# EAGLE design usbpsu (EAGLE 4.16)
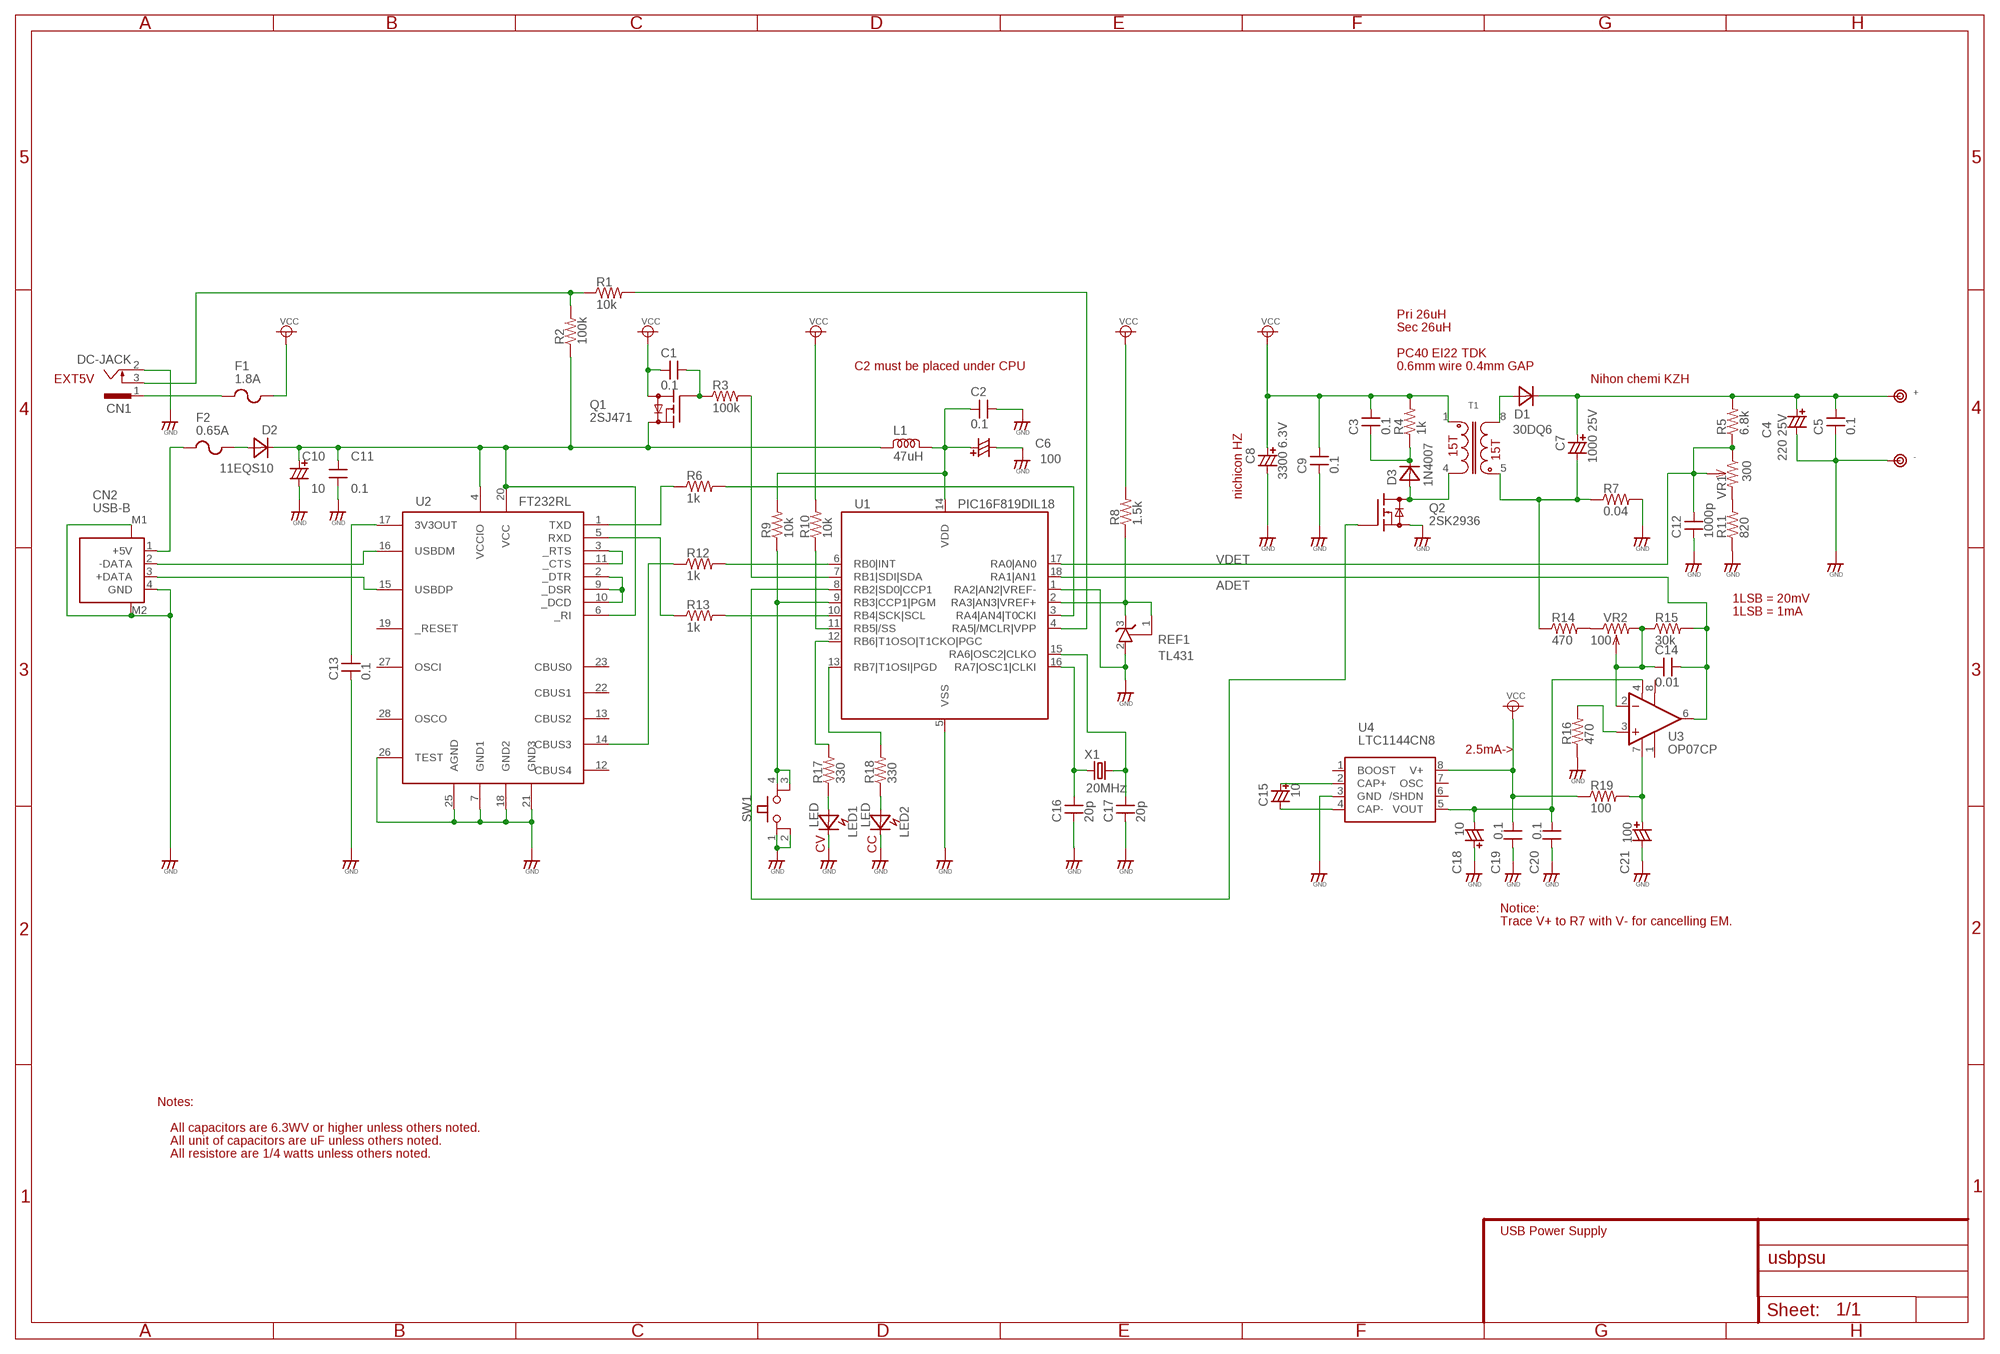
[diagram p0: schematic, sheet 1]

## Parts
+  TERM  [TERM_ARMY]
-  TERM  [TERM_ARMY]
C1  0.1  CAPDIP_2  [CAP_DIP_2]
C2  0.1  CAPSM2012  [C2012]
C3  0.1  CAPDIP_2  [CAP_DIP_2]
C4  220 25V  CCAP8  [CCAP_8]
C5  0.1  CAPDIP_2  [CAP_DIP_2]
C6  100  CCAP5.2  [CCAP_5.2]
C7  1000 25V  CCAP10.5  [CCAP_10.5]
C8  3300 6.3V  CCAP10.5  [CCAP_10.5]
C9  0.1  CAPDIP_2  [CAP_DIP_2]
C10  10  CCAP5.2  [CCAP_5.2]
C11  0.1  CAPDIP_2  [CAP_DIP_2]
C12  1000p  CAPDIP_2  [CAP_DIP_2]
C13  0.1  CAPDIP_2  [CAP_DIP_2]
C14  0.01  CAPDIP_2  [CAP_DIP_2]
C15  10  CCAP5.2  [CCAP_5.2]
C16  20p  CAPDIP_1  [CAP_DIP_1]
C17  20p  CAPDIP_1  [CAP_DIP_1]
C18  10  CCAP5.2  [CCAP_5.2]
C19  0.1  CAPDIP_2  [CAP_DIP_2]
C20  0.1  CAPDIP_2  [CAP_DIP_2]
C21  100  CCAP5.2  [CCAP_5.2]
CN1  DC-JACK  DC-JACK2DC0005D100  [2DC0005D100]
CN2  USB-B  [85-32004-00X]
D1  30DQ6  DIODEGENERIC_5  [DIODE_5]
D2  11EQS10  DIODEGENERIC_2  [DIODE_2]
D3  1N4007  DIODEGENERIC_3  [DIODE_3]
F1  1.8A  POLYSW10X3MM  [AX_10X03_2P_200]
F2  0.65A  POLYSW8X2MM  [AX_08X02_2P_200]
L1  47uH  MICRO_INDUCTOR  [LAL02]
LED1  LED  [LED_3MM_VIRT_2]
LED2  LED  [LED_3MM_VIRT_2]
Q1  2SJ471  [TO220-VIRT]
Q2  2SK2936  [TO220-VIRT]
R1  10k  R0.125W_2P  [R_0.125W_2]
R2  100k  R0.125W_2P  [R_0.125W_2]
R3  100k  R0.125W_2P  [R_0.125W_2]
R4  1k  R0.125W_2P  [R_0.125W_2]
R5  6.8k  R0.125W_2P  [R_0.125W_2]
R6  1k  R0.125W_2P  [R_0.125W_2]
R7  0.04  RSMD6332  [R6332]
R8  1.5k  R0.125W_2P  [R_0.125W_2]
R9  10k  R0.125W_2P  [R_0.125W_2]
R10  10k  R0.125W_2P  [R_0.125W_2]
R11  820  R0.125W_2P  [R_0.125W_2]
R12  1k  R0.125W_2P  [R_0.125W_2]
R13  1k  R0.125W_2P  [R_0.125W_2]
R14  470  R0.125W_2P  [R_0.125W_2]
R15  30k  R0.125W_2P  [R_0.125W_2]
R16  470  R0.125W_2P  [R_0.125W_2]
R17  330  R0.125W_2P  [R_0.125W_2]
R18  330  R0.125W_2P  [R_0.125W_2]
R19  100  R0.125W_2P  [R_0.125W_2]
REF1  TL431  TL431CLP  [TO92]
SW1  PUSHSW-6MM  [PUSHSW-6MM]
T1  TRANS  [TDK_BE22]
U1  PIC16F819DIL18  [DIL18]
U2  FT232RL  [SSOP28DB]
U3  OP07CP  [DIL08]
U4  LTC1144CN8  [DIL08]
VR1  300  VR  [VR-7MM]
VR2  100  VR  [VR-7MM]
X1  20MHz  CRYSTALHC49S  [HC49/S]

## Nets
/BUSPWR: R3.2 U1.7(RB1|SDI|SDA)
/PWREN: R12.1 U2.14(CBUS3)
ADET: C14.2 R15.2 U1.18(RA1|AN1) U3.6(OUT)
DVCC: C1.1 C3.2 C8.+ C9.2 C19.2 F1.2 Q1.2(D) R4.2 R8.2 R10.2 R19.1 T1.1 U4.8(V+) ; supply symbol labelled VCC
EXTDET: R1.2 U1.4(RA5|/MCLR|VPP)
GND: -.1(TERM) C2.2 C4.- C5.1 C6.- C8.- C9.1 C10.- C11.1 C12.1 C13.1 C16.1 C17.1 C18.+ C19.1 C20.1 C21.- CN1.2 CN2.4(GND) CN2.M1(FG1) CN2.M2(FG2) LED1.K LED2.K Q2.3(S) R7.2 R11.1 R16.1 REF1.2(A) SW1.1 SW1.2 U1.1(RA2|AN2|VREF-) U1.5(VSS) U2.7(GND1) U2.18(GND2) U2.21(GND3) U2.25(AGND) U2.26(TEST) U4.3(GND)
N$1: CN1.3 R1.1 R2.2
N$2: R9.1 SW1.3 SW1.4 U1.9(RB3|CCP1|PGM)
N$3: C13.2 U2.17(3V3OUT)
N$4: C18.- C20.2 U3.4(V-) U4.5(VOUT)
N$5: C2.1 C6.+ L1.2 R9.2 U1.14(VDD)
N$6: LED1.A R17.1
N$7: C16.2 U1.16(RA7|OSC1|CLKI) X1.1
N$8: C17.2 U1.15(RA6|OSC2|CLKO) X1.2
N$9: LED2.A R18.1
N$10: C21.+ R19.2 U3.7(V+)
N$11: U2.3(_RTS) U2.11(_CTS)
N$12: R17.2 U1.12(RB6|T1OSO|T1CKO|PGC)
N$13: R18.2 U1.13(RB7|T1OSI|PGD)
N$14: C15.+ U4.2(CAP+)
N$15: C15.- U4.4(CAP-)
N$16: C10.+ C11.2 D2.K L1.1 Q1.3(S) R2.1 U2.4(VCCIO) U2.6(_RI) U2.20(VCC)
N$17: C3.1 D3.K R4.1
N$18: R14.2 VR2.1
N$19: +.1(TERM) C4.+ C5.2 C7.+ D1.K R5.2
N$20: C14.1 R15.1 U3.2(-IN) VR2.2 VR2.3
N$21: D3.A Q2.2(D) T1.4(P2)
N$22: C1.2 Q1.1(G) R3.1
N$23: R6.1 U2.1(TXD)
N$24: R12.2 U1.6(RB0|INT)
N$25: D1.A T1.8(S1)
N$26: D2.A F2.2
N$27: R13.2 U1.10(RB4|SCK|SCL)
N$28: CN2.1(+5V) F2.1
N$30: C7.- R7.1 R14.1 T1.5(S2)
N$31: R8.1 REF1.1(R) REF1.3(C) U1.2(RA3|AN3|VREF+)
N$33: R11.2 VR1.3
N$34: R16.2 U3.3(+IN)
N$35: CN1.1 F1.1
N$36: U2.2(_DTR) U2.9(_DSR) U2.10(_DCD)
N$37: R10.1 U1.11(RB5|/SS)
PWM: Q2.1(G) U1.8(RB2|SD0|CCP1)
RXD: R13.1 U2.5(RXD)
TXD: R6.2 U1.3(RA4|AN4|T0CKI)
USB+: CN2.3(+DATA) U2.15(USBDP)
USB-: CN2.2(-DATA) U2.16(USBDM)
VDET: C12.2 R5.1 U1.17(RA0|AN0) VR1.1 VR1.2
Unconnected: U2.12(CBUS4) U2.13(CBUS2) U2.19(_RESET) U2.22(CBUS1) U2.23(CBUS0) U2.27(OSCI) U2.28(OSCO) U3.1(TRIM1) U3.8(TRIM2) U4.1(BOOST) U4.6(/SHDN) U4.7(OSC)

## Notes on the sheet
- Pri 26uH
- Sec 26uH
- PC40 EI22 TDK
- C2 must be placed under CPU | 0.6mm wire 0.4mm GAP
- EXT5V | Nihon chemi KZH
- 15T
- 15T
- nichicon HZ
- 1LSB = 20mV
- 1LSB = 1mA
- 2.5mA->
- CV | CC
- Notice:
- Trace V+ to R7 with V- for cancelling EM.
- Notes:
- All capacitors are 6.3WV or higher unless others noted.
- All unit of capacitors are uF unless others noted.
- All resistore are 1/4 watts unless others noted.
- USB Power Supply

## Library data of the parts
+ - = usbpsu:TERM
C1-C3 C5 C9 C11-C14 C16 C17 C19 C20 = usbpsu:CAP: Non polar capacitor
C4 C6-C8 C10 C15 C18 C21 = usbpsu:CCAP: Polar capacitor
CN1 = usbpsu:DC-JACK
CN2 = usbpsu:USB-B: USB-B Connector
D1-D3 = usbpsu:DIODE
F1 F2 = usbpsu:POLYSW
L1 = usbpsu:MICRO_INDUCTOR
LED1 LED2 = usbpsu:LED
Q1 = usbpsu:2SJ471
Q2 = usbpsu:2SK2936
R1-R19 = usbpsu:R
REF1 = usbpsu:TL431CLP: VOLTAGE REGULATOR
SW1 = usbpsu:PUSHSW-6MM
T1 = usbpsu:TRANS
U1 = usbpsu:PIC16F819: PIC MICRO (16 I/O 10bit-5ch ADC 20MHz)
U2 = ftdichip:FT232RL: USB UART 4th Generation USB UART (USB <-> Serial) Controller
U3 = usbpsu:OP07C
U4 = usbpsu:LTC1144
VR1 VR2 = usbpsu:VR
X1 = usbpsu:CRYSTAL: CRYSTAL

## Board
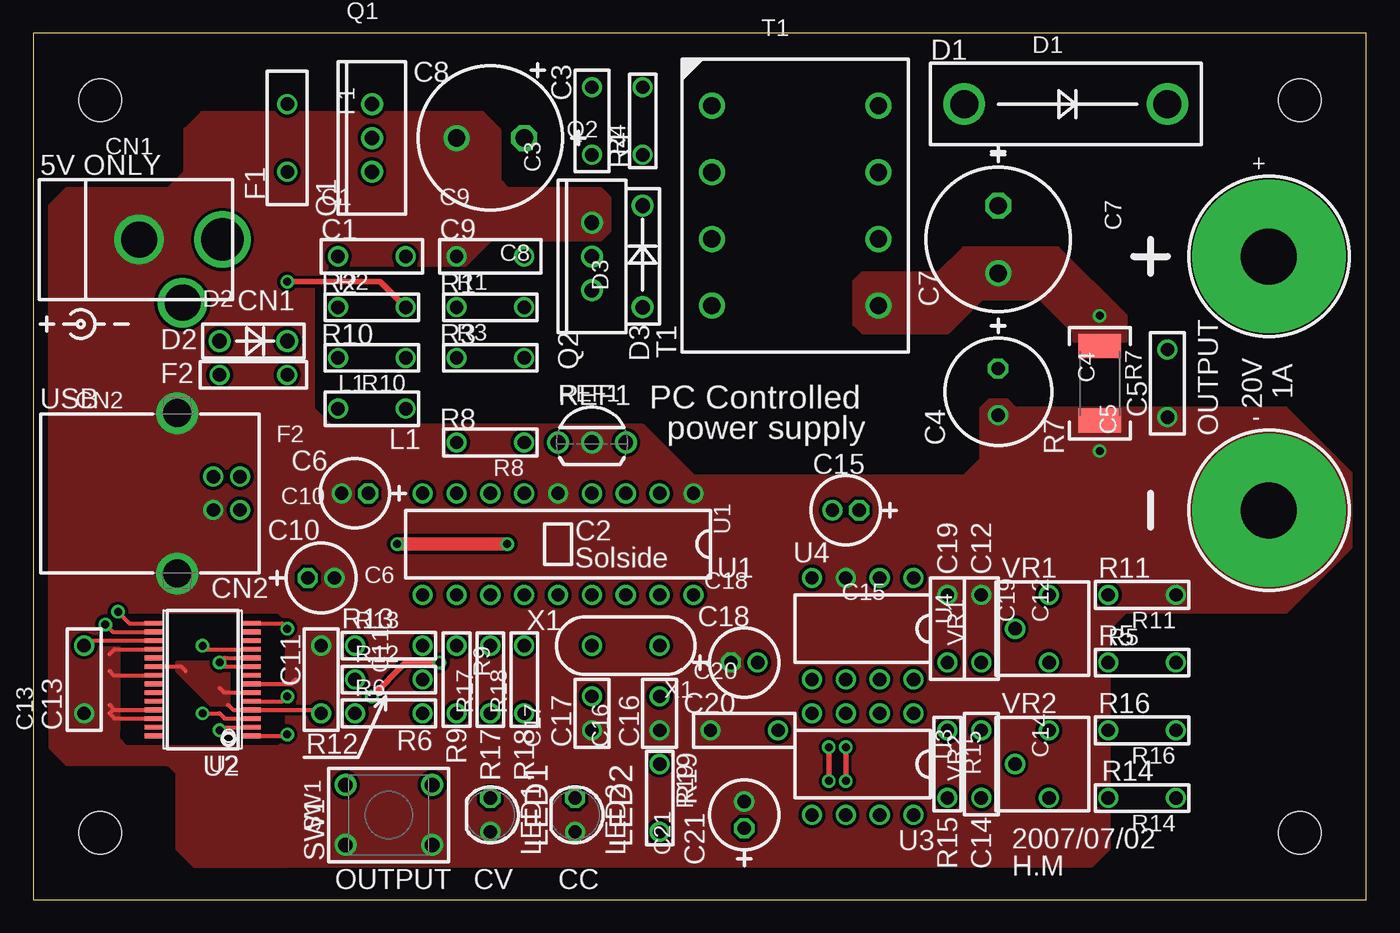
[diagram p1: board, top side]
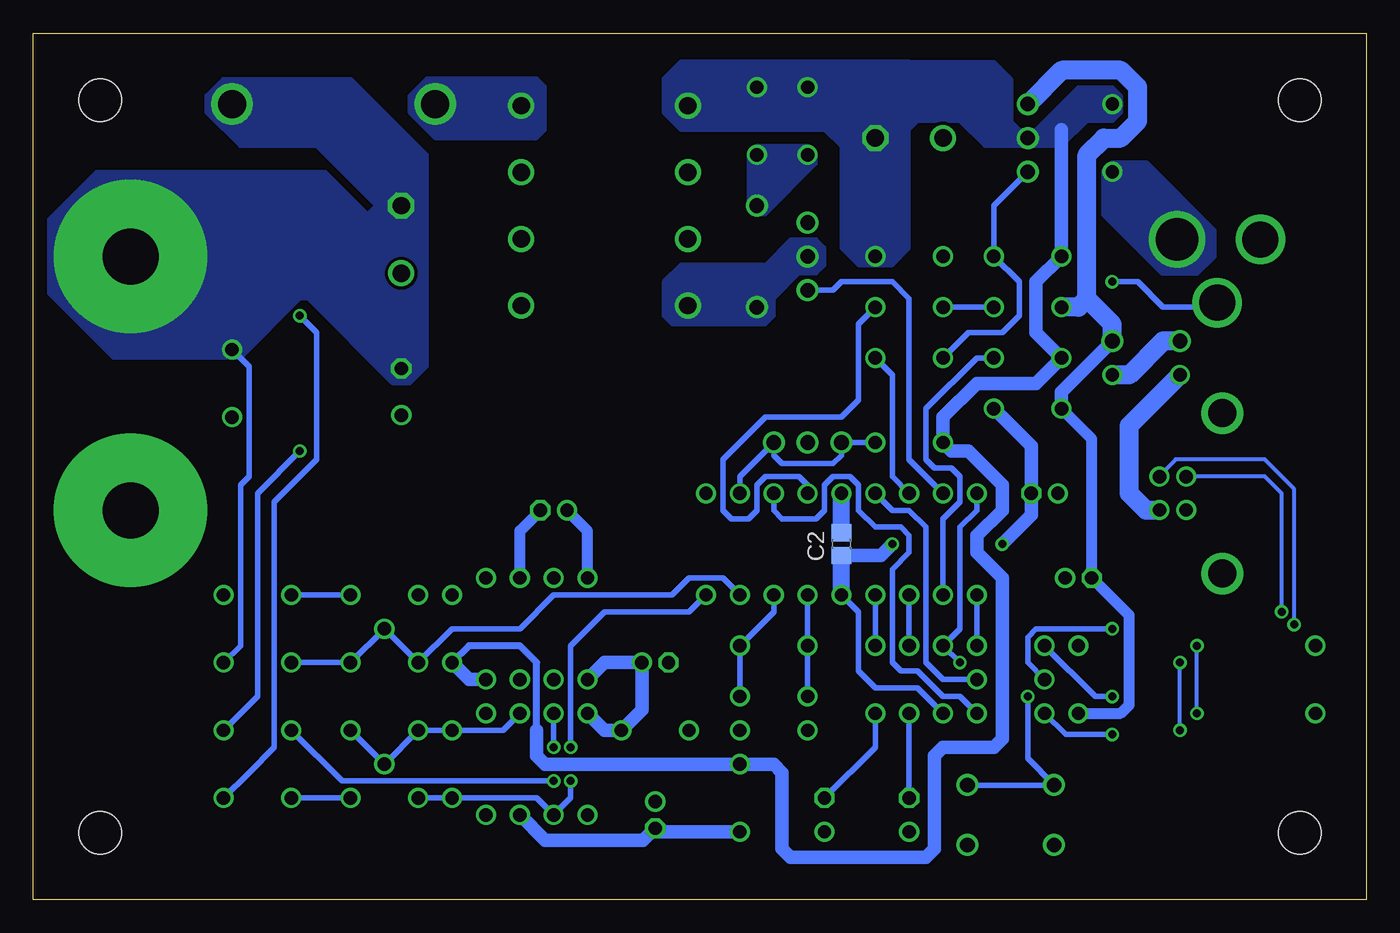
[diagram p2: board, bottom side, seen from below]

Size 100 x 65 mm. Coordinates in mm from the lower left corner, seen from the top.
Outline: 0,0 100,0 100,65 0,65 0,0
Copper layers (1*16): Top 0.035mm / dielectric 1.5mm / Bottom 0.035mm
Design rules "Olimex10mils": minimum track width 10mil, minimum drill 0.6mm, track to track 10mil, track to pad 10mil, pad to pad 10mil, via to via 10mil, smd to smd 10mil, copper to edge 40mil, drill to drill 10mil, minimum pad ring 10mil, minimum via ring 8mil, stop-mask expansion 0mil, vias tented up to drill 0mil, thermal gap 10mil
Holes 3.2 mm at 95,60 95,5 5,5 5,60
tRestrict: area 90,55 to 100,65; area 90,0 to 100,10; area 0,0 to 10,10; area 0,55 to 10,65
bRestrict: area 0,55 to 10,65; area 0,0 to 10,10; area 90,55 to 100,65; area 90,0 to 100,10

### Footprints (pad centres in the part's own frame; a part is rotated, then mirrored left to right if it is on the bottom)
TERM_ARMY = drill 4.2 pad 11.5 round: 1 0,0
CAP_DIP_2 = drill 1 round: 1 -2.54,0; 2 2.54,0
C2012 = smd 1.3 x 1.5: 1 -0.85,0; 2 0.85,0
CCAP_8 = drill 1 octagon: + -1.75,0 | drill 1 round: - 1.75,0
CCAP_5.2 = drill 1 octagon: + -1,0 | drill 1 round: - 1,0
CCAP_10.5 = drill 1.3 octagon: + -2.54,0 | drill 1.3 round: - 2.54,0
CAP_DIP_1 = drill 1 round: 1 -1.27,0; 2 1.27,0
2DC0005D100 = drill 3.2 round: 1 6.25,0 | drill 2.7 round: 2 0,0; 3 3.25,-4.75
85-32004-00X = drill 1 round: 1 4.71,-1.25; 2 4.71,1.25; 3 2.71,1.25; 4 2.71,-1.25 | drill 2.1 round: M1 0,6.02; M2 0,-6.02
DIODE_5 = drill 2.1 round: A -7.62,0; K 7.62,0
DIODE_2 = drill 1.1 round: A -2.54,0; K 2.54,0
DIODE_3 = drill 1.1 round: A -3.81,0; K 3.81,0
AX_10X03_2P_200 = drill 1 round: 1 2.54,0; 2 -2.54,0
AX_08X02_2P_200 = drill 1 round: 1 2.54,0; 2 -2.54,0
LAL02 = drill 1 round: 1 -2.54,0; 2 2.54,0
LED_3MM_VIRT_2 = drill 1 octagon: A -1.27,0 | drill 1 round: K 1.27,0
TO220-VIRT = drill 1.1 round: 1 0,-2.54; 2 0,0; 3 0,2.54
R_0.125W_2 = drill 1 round: 1 -2.54,0; 2 2.54,0
R6332 = smd 1.8 x 3.2: 1 -2.8,0; 2 2.8,0
TO92 = drill 1.1 round: 1 -2.54,0; 2 0,0; 3 2.54,0
PUSHSW-6MM = drill 1.1 round: 1 -2.25,3.25; 2 -2.25,-3.25; 3 2.25,-3.25; 4 2.25,3.25
TDK_BE22 = drill 1.3 round: 1 -6.25,7.5; 2 -6.25,2.5; 3 -6.25,-2.5; 4 -6.25,-7.5; 5 6.25,-7.5; 6 6.25,-2.5; 7 6.25,2.5; 8 6.25,7.5
DIL18 = drill 1 round: 1 -10.16,-3.81; 2 -7.62,-3.81; 3 -5.08,-3.81; 4 -2.54,-3.81; 5 0,-3.81; 6 2.54,-3.81; 7 5.08,-3.81; 8 7.62,-3.81; 9 10.16,-3.81; 10 10.16,3.81; 11 7.62,3.81; 12 5.08,3.81; 13 2.54,3.81; 14 0,3.81; 15 -2.54,3.81; 16 -5.08,3.81; 17 -7.62,3.81; 18 -10.16,3.81
SSOP28DB = smd 0.348 x 1.397: 1 -4.225,-3.656; 2 -3.575,-3.656; 3 -2.925,-3.656; 4 -2.275,-3.656; 5 -1.625,-3.656; 6 -0.975,-3.656; 7 -0.325,-3.656; 8 0.325,-3.656; 9 0.975,-3.656; 10 1.625,-3.656; 11 2.275,-3.656; 12 2.925,-3.656; 13 3.575,-3.656; 14 4.225,-3.656; 15 4.225,3.656; 16 3.575,3.656; 17 2.925,3.656; 18 2.275,3.656; 19 1.625,3.656; 20 0.975,3.656; 21 0.325,3.656; 22 -0.325,3.656; 23 -0.975,3.656; 24 -1.625,3.656; 25 -2.275,3.656; 26 -2.925,3.656; 27 -3.575,3.656; 28 -4.225,3.656
DIL08 = drill 1 round: 1 -3.81,-3.81; 2 -1.27,-3.81; 3 1.27,-3.81; 4 3.81,-3.81; 5 3.81,3.81; 6 1.27,3.81; 7 -1.27,3.81; 8 -3.81,3.81
VR-7MM = drill 1 round: 1 -2.54,0; 2 0,2.54; 3 2.54,0
HC49/S = drill 1 round: 1 -2.54,0; 2 2.54,0

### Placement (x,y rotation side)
+  92.71,48.26 0 top
-  92.71,29.21 0 top
C1  25.4,48.26 0 top
C2  39.37,26.67 90 bottom
C3  41.91,58.42 90 top
C4  72.39,38.1 270 top
C5  85.09,38.73 90 top
C6  24.13,30.48 180 top
C7  72.39,49.53 270 top
C8  34.29,57.15 180 top
C9  34.29,48.26 0 top
C10  21.59,24.13 0 top
C11  21.59,16.51 270 top
C12  71.12,20.32 270 top
C13  3.81,16.51 90 top
C14  71.12,10.16 270 top
C15  60.96,29.21 180 top
C16  46.99,13.97 90 top
C17  41.91,13.97 90 top
C18  53.34,17.78 0 top
C19  68.58,20.32 270 top
C20  53.34,12.7 0 top
C21  53.34,6.35 90 top
CN1  7.94,49.53 0 top
CN2  10.79,30.48 0 top
D1  77.47,59.69 0 top
D2  16.51,41.91 0 top
D3  45.72,48.26 90 top
F1  19.05,57.15 270 top
F2  16.51,39.37 180 top
L1  25.4,36.83 0 top
LED1  34.29,6.35 270 top
LED2  40.64,6.35 270 top
Q1  25.4,57.15 0 top
Q2  41.91,48.26 0 top
R1  34.29,44.45 0 top
R2  25.4,44.45 0 top
R3  34.29,40.64 0 top
R4  45.72,58.42 90 top
R5  83.19,17.78 0 top
R6  26.67,13.97 0 top
R7  80.01,38.73 270 top
R8  34.29,34.29 180 top
R9  31.75,16.51 270 top
R10  25.4,40.64 180 top
R11  83.19,22.86 180 top
R12  26.67,16.51 0 top
R13  26.67,19.05 0 top
R14  83.19,7.62 180 top
R15  68.58,10.16 270 top
R16  83.19,12.7 180 top
R17  34.29,16.51 90 top
R18  36.83,16.51 90 top
R19  46.99,7.62 270 top
REF1  41.91,34.29 0 top
SW1  26.67,6.35 90 top
T1  57.15,52.07 0 top
U1  39.37,26.67 180 top
U2  12.7,16.51 90 top
U3  62.23,10.16 180 top
U4  62.23,20.32 180 top
VR1  76.2,20.32 90 top
VR2  76.2,10.16 90 top
X1  44.45,19.05 180 top

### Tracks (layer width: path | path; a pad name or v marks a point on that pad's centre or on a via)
/BUSPWR
  Bottom 0.406: R3.2 35.56,39.37 35.56,31.75 U1.7
/PWREN  (via drill 0.6)
  Top 0.305: U2.14 18.64,20.73 v19.05,20.32
  Bottom 0.406: R12.1 25.4,17.78 25.4,19.68 24.77,20.32 v19.05,20.32
ADET  (via drill 0.6)
  Top 0.406: v59.69,8.89 v59.69,11.43
  Bottom 0.406: U1.18 50.8,21.59 57.15,21.59 59.69,19.05 v59.69,11.43 | v59.69,8.89 59.69,7.62 U3.6 62.23,7.62 R15.2 C14.2
DVCC
  Bottom 0.508: 62.23,12.7 62.23,17.78 63.5,19.05 67.31,19.05 C19.2
  Bottom 1.016: 22.86,57.78 C1.1 24.77,46.35 24.77,42.55 R10.2 24.77,38.73 29.21,38.73 31.75,36.2 R8.2 31.11,33.66 29.84,33.66 27.3,31.11 27.3,29.21 29.21,27.3 29.21,26.04 27.3,24.13 27.3,23.5 27.3,12.06 27.94,11.43 31.75,11.43 32.38,10.79 32.38,3.81 33.02,3.17 43.18,3.17 43.81,3.81 43.81,9.53 44.45,10.16 R19.1 47.62,10.16 49.53,10.16 57.15,10.16 58.42,10.16 61.59,10.16 62.23,10.79 62.23,12.7 | C19.2 67.31,16.51 U4.8
  pour Bottom (no thermals): 34.29,62.87 51.44,62.87 52.7,61.59 52.7,59.05 51.44,57.78 40.64,57.78 39.37,56.52 39.37,48.9 38.1,47.62 35.56,47.62 34.29,48.9
  pour Bottom (no thermals): 34.29,62.87 27.94,62.87 26.67,61.59 26.67,58.42 26.04,57.78 24.77,57.78 21.59,60.96 19.05,60.96 18.41,60.33 18.41,59.05 19.05,58.42 20.95,58.42 22.86,56.52 28.57,56.52 30.48,58.42 33.66,58.42 34.29,57.78
EXTDET
  Bottom 0.406: U1.4 41.91,31.11 42.55,31.75 45.09,31.75 45.72,31.11 45.72,29.21 46.35,28.57 47.62,28.57 48.26,29.21 48.26,33.02 45.09,36.2 39.37,36.2 38.1,37.47 38.1,43.18 R1.2
GND  (via drill 0.6)
  Top 0.305: U2.21 6.03,16.84 5.71,17.14 | U2.7 19.36,16.18 19.68,16.51 | 6.08,14.23 U2.25 | 6.08,14.23 5.71,14.61 | 6.08,14.23 5.98,14.23 5.71,13.97 6.1,13.59 U2.26 | U2.18 6.08,18.79 5.71,18.41
  Bottom 0.406: R16.1 83.19,15.24 83.19,22.86 83.19,24.13 83.19,30.48 v80.01,33.66
  Bottom 1.27: C2.2 U1.5
  pour Top (no thermals): 11.43,57.78 12.7,59.05 33.66,59.05 34.92,57.78 34.92,53.98 35.56,53.34 42.55,53.34 43.18,52.7 43.18,50.16 42.55,49.53 34.29,49.53 32.38,47.62 11.43,47.62
  pour Top (no thermals): 22.23,47.62 20.95,46.35 20.95,36.83 22.23,35.56 45.72,35.56 49.53,31.75 69.85,31.75 71.12,33.02 71.12,36.83 71.75,37.47 73.03,37.47 73.66,36.83 93.98,36.83 99.06,31.75 99.06,26.67 93.98,21.59 81.92,21.59 80.64,20.32 80.64,3.81 79.38,2.54 19.05,2.54 19.05,20.95 18.41,21.59 6.99,21.59 6.35,20.95 6.35,12.7 1.27,12.7 1.27,52.07 2.54,53.34 10.16,53.34 11.43,54.61 12.7,54.61 12.7,49.53 22.23,49.53
  pour Top: 19.05,12.06 18.41,11.43 6.99,11.43 6.35,12.06 6.35,15.24 1.27,15.24 1.27,11.43 2.54,10.16 10.16,10.16 10.79,9.53 10.79,3.81 12.06,2.54 19.05,2.54
N$1  (via drill 0.6)
  Top 0.406: v19.05,46.35 26.04,46.35 R2.2
  Bottom 0.406: R2.2 R1.1 | CN1.3 11.19,44.45 15.24,44.45 17.14,46.35 v19.05,46.35
N$2  (via drill 0.6)
  Top 0.406: v25.4,15.24 27.94,17.78 v30.48,17.78
  Bottom 0.406: v30.48,17.78 R9.1 30.48,20.32 30.48,27.94 29.21,29.21 U1.9 | SW1.3 29.89,8.57 23.45,8.57 SW1.4 25.4,10.58 v25.4,15.24
N$3
  Top 0.317: U2.17 3.81,19.43 C13.2
N$4
  Bottom 1.016: U4.5 57.15,17.78 54.61,17.78 C18.- 54.34,14.24 C20.2 57.15,12.7 U3.4
N$5  (via drill 0.6)
  Top 1.016: v35.56,26.67 v27.3,26.67
  Bottom 0.406: R9.2 33.66,15.88 36.83,15.88 38.1,17.14 38.1,21.59 U1.14
  Bottom 1.016: L1.2 25.13,34.02 C6.+ 25.13,28.84 v27.3,26.67 | C2.1 36.41,25.82 v35.56,26.67
  Bottom 1.27: U1.14 C2.1
N$6
  Bottom 0.406: LED1.A R17.1
N$7
  Bottom 0.406: U1.16 44.45,21.59 X1.1 C16.2
N$8
  Bottom 0.406: U1.15 X1.2 C17.2
N$9
  Bottom 0.406: R18.1 36.83,11.43 LED2.A
N$10
  Bottom 1.016: R19.2 53.07,5.08 C21.+ 54.24,4.45 61.59,4.45 U3.7
N$11  (via drill 0.6)
  Top 0.305: U2.11 12.96,18.79 v12.7,19.05 | U2.3 14.36,13.59 13.97,13.97 v12.7,13.97
  Bottom 0.305: v12.7,13.97 v12.7,19.05
N$12
  Bottom 0.406: R17.2 U1.12
N$13
  Bottom 0.406: R18.2 U1.13
N$14
  Bottom 0.813: C15.+ 63.5,27.67 U4.2
N$15
  Bottom 0.813: C15.- 58.42,27.67 U4.4
N$16
  Top 0.305: 11.43,17.14 11.09,17.48 U2.20 | C11.2 21.32,14.23 U2.4 14.97,14.23 14.61,14.61 | U2.6 14.31,15.54 13.97,15.88
  Bottom 0.813: C11.2 18.41,13.97 17.78,14.61 17.78,21.32 C10.+ 20.59,34.56 L1.1
  Bottom 1.016: D2.K 22.86,38.1 L1.1
  Bottom 1.422: Q1.3 22.86,62.23 18.41,62.23 17.14,60.96 17.14,58.42 18.41,57.15 19.68,57.15 20.95,55.88 20.95,45.09 | R2.1 21.59,44.45 20.95,45.09 | 20.95,45.09 19.05,43.18 D2.K
  pour Top: 10.79,17.78 14.61,17.78 14.61,14.61 13.34,14.61 10.79,17.14
N$17
  pour Bottom (no thermals): 41.27,55.88 41.91,56.52 45.72,56.52 46.35,55.88 46.35,52.07 45.72,51.44 45.09,51.44 41.27,55.24
N$18
  Bottom 0.406: VR2.1 R14.2
N$19
  Bottom 0.406: C5.2 83.82,40.01 83.82,31.75 84.45,31.11 84.45,26.04 84.45,20.32 84.45,19.05 R5.2
  pour Bottom (no thermals): 85.72,61.59 76.2,61.59 70.48,55.88 70.48,40.01 71.75,38.73 73.03,38.73 79.38,45.09 80.01,45.09 84.45,40.64 93.98,40.64 99.06,45.72 99.06,50.8 95.25,54.61 78.11,54.61 74.93,51.44 74.3,52.07 78.74,56.52 84.45,56.52 87,59.05 87,60.33
N$20
  Bottom 0.406: U3.2 64.77,12.7 R15.1 C14.1 VR2.2 VR2.3
N$21
  pour Bottom (no thermals): 41.27,49.53 43.18,49.53 45.09,47.62 51.44,47.62 52.7,46.35 52.7,43.81 52.07,43.18 45.09,43.18 44.45,43.81 44.45,45.09 42.55,46.99 41.27,46.99 40.64,47.62 40.64,48.9
N$22
  Bottom 0.406: Q1.1 27.94,52.07 C1.2 26.04,46.35 26.04,43.81 27.3,42.55 29.84,42.55 R3.1
N$23  (via drill 0.6)
  Top 0.305: U2.1 18.95,12.29 v19.05,12.38
  Bottom 0.406: v19.05,12.38 22.54,12.38 R6.1
N$24
  Bottom 0.406: U1.6 35.56,29.21 34.29,29.21 33.02,27.94 33.02,25.4 33.02,17.78 31.75,16.51 R12.2
N$25
  pour Bottom (no thermals): 61.59,60.96 62.23,61.59 70.48,61.59 71.75,60.33 71.75,59.05 69.85,57.15 62.23,57.15 61.59,57.78
N$26
  Bottom 1.422: F2.2 17.78,39.37 15.24,41.91 D2.A
N$27
  Bottom 0.406: R13.2 U1.10
N$28
  Bottom 1.422: F2.1 17.78,35.56 17.78,31.5 17.78,31.11 17.78,30.48 16.51,29.21 15.88,29.21 15.53,29.21 CN2.1
N$30  (via drill 0.6)
  Top 0.406: R7.1 80.01,41.91
  Bottom 0.406: R14.1 83.82,9.53 81.92,11.43 81.92,12.7 81.92,29.84 78.74,33.02 78.74,42.55 v80.01,43.81
  pour Top (no thermals): 62.23,46.99 67.94,46.99 69.85,48.9 76.83,48.9 81.92,43.81 81.92,41.91 78.11,41.91 78.11,42.55 75.56,45.09 71.12,45.09 68.58,42.55 62.23,42.55 61.59,43.18 61.59,46.35
N$31
  Bottom 0.406: R8.1 REF1.1 39.37,33.34 40.01,32.7 43.81,32.7 44.45,33.34 REF1.3 46.99,31.75 U1.2
N$33
  Bottom 0.406: VR1.3 R11.2
N$34  (via drill 0.6)
  Top 0.406: v60.96,8.89 v60.96,11.43
  Bottom 0.406: R16.2 76.83,8.89 v60.96,8.89 | v60.96,11.43 U3.3
N$35
  pour Bottom (no thermals): 16.51,55.24 11.43,50.16 11.43,48.26 12.7,46.99 15.24,46.99 19.68,51.44 19.68,54.61 19.05,55.24
N$36  (via drill 0.6)
  Top 0.305: U2.10 14.32,18.14 v13.97,17.78 14.27,17.48 U2.9 | U2.2 14.21,12.94 v13.97,12.7
  Bottom 0.305: v13.97,12.7 v13.97,17.78
N$37
  Bottom 0.406: U1.11 31.75,28.57 30.48,29.84 30.48,31.75 31.11,32.38 32.38,32.38 33.02,33.02 33.02,36.83 29.21,40.64 R10.1
PWM
  Bottom 0.406: Q2.1 40.01,45.72 39.37,46.35 35.56,46.35 34.29,45.09 34.29,33.02 U1.8
RXD  (via drill 0.6)
  Top 0.305: U2.5 18.7,14.88 v19.05,15.24
  Bottom 0.406: v19.05,15.24 20.32,15.24 R13.1
TXD
  Bottom 0.406: U1.3 44.45,29.21 43.81,28.57 41.27,28.57 40.64,29.21 40.64,31.11 40.01,31.75 38.73,31.75 38.1,31.11 38.1,29.21 36.83,27.94 36.2,27.94 34.92,27.94 34.29,27.3 34.29,26.04 35.56,24.77 35.56,17.78 34.92,17.14 33.66,17.14 31.75,15.24 30.48,15.24 R6.2
USB+  (via drill 0.6)
  Top 0.305: U2.15 7.21,20.73 v6.35,21.59
  Bottom 0.305: v6.35,21.59 6.35,30.48 7.62,31.75 13.48,31.75 CN2.3
USB-  (via drill 0.6)
  Top 0.305: U2.16 5.95,20.09 v5.4,20.64
  Bottom 0.305: v5.4,20.64 5.4,30.8 7.62,33.02 14.29,33.02 15.56,31.75 15.53,31.75 CN2.2
VDET
  Bottom 0.406: U1.17 48.26,24.13 50.8,24.13 52.07,22.86 60.96,22.86 63.5,20.32 68.58,20.32 C12.2 VR1.2 VR1.1 R5.1

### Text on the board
Document: 75mm | 100mm
_tPlace: SW1
_tNames: D1 | C8 | C3 | F1 | R4 | 5V ONLY | Q1 | C1 | C9 | R2 | R1 | CN1 | C7 | R10 | R3 | D2 | T1 | Q2 | D3 | F2 | 1A | USB | REF1 | PC Controlled | 20V | C5 | R8 | power supply | OUTPUT | L1 | C4 | R7 | C6 | C15 | C10 | C2 | Solside | U4 | U1 | C19 | C12 | VR1 | R11 | CN2 | X1 | R13 | C18 | R5 | C11 | C20 | VR2 | R16 | C13 | R6 | R12 | U2 | C17 | C16 | R9 | R17 | R18 | R14 | R19 | U3 | 2007/07/02 | LED1 | LED2 | C21 | R15 | C14 | H.M | OUTPUT | CV | CC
